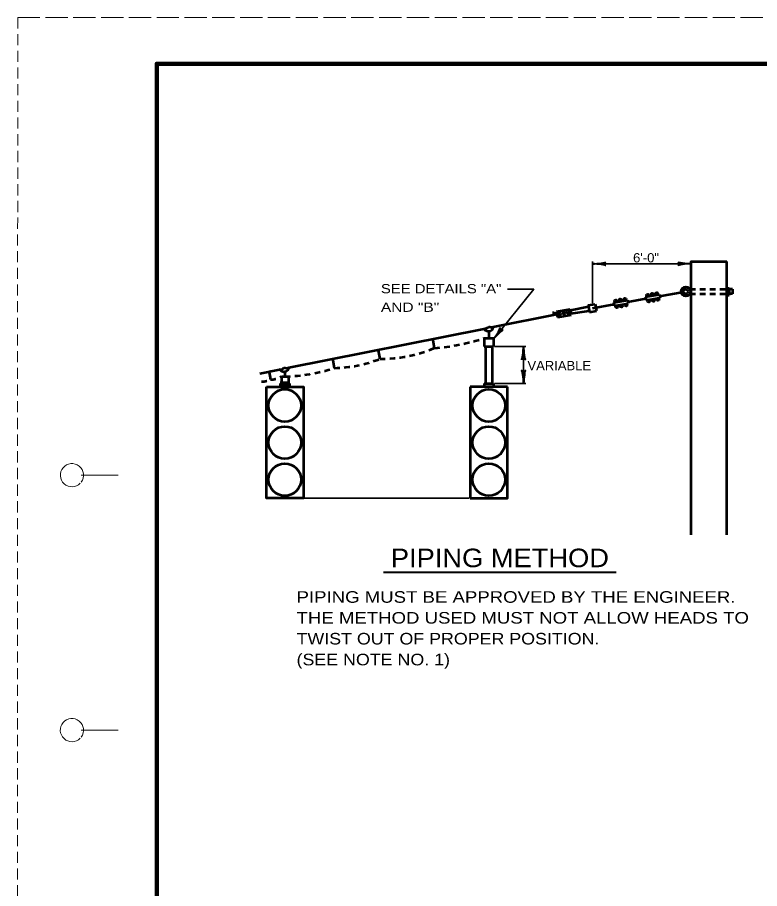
# Model space of a CAD drawing. Extents: x -286 to 394, y -156 to 284.
# Drawn here: x -286.4 to -126.2, y 96.5 to 284.5 of the extents above; entities that cross this region are included whole.
import ezdxf
from ezdxf.enums import TextEntityAlignment as Align

# ---------------------------------------------------------------- set-up
doc = ezdxf.new("R2010")
doc.units = 0
doc.header["$LTSCALE"] = 0.8
for name, pattern in [('LONG_DASHED', [7.5, 6, -1.5]), ('MEDIUM_DASHED', [4.5, 3, -1.5]), ('SHORT_DASHED', [2.7, 1.5, -1.2])]:
    doc.linetypes.add(name, pattern=pattern)
doc.layers.add('1', color=7, linetype='Continuous', lineweight=53)
doc.layers.add('61', color=7, linetype='Continuous', lineweight=35)

msp = doc.modelspace()

# ---------------------------------------------------------------- hatches: boundary and pattern name
at = {"layer": '1'}
for points in [[(-156.0439, 223.4737, 1), (-156.5439, 223.4737, 1)], [(-155.0623, 223.6436, 1), (-155.5623, 223.6436, 1)], [(-150.1246, 224.52, 1), (-150.6246, 224.52, 1)], [(-149.1505, 224.6899, 1), (-149.6505, 224.6899, 1)], [(-148.8976, 223.4474, 1), (-149.3976, 223.4474, 1)], [(-148.1689, 224.8598, 1), (-148.6689, 224.8598, 1)], [(-147.9197, 223.6212, 1), (-148.4197, 223.6212, 1)], [(-157.018, 223.3037, 1), (-157.518, 223.3037, 1)], [(-156.7877, 222.0499, 1), (-157.2877, 222.0499, 1)], [(-155.791, 222.2312, 1), (-156.291, 222.2312, 1)], [(-154.8132, 222.4049, 1), (-155.3132, 222.4049, 1)], [(-149.8943, 223.2662, 1), (-150.3943, 223.2662, 1)], [(-169.2135, 220.5049, 1), (-169.7135, 220.5049, 1)], [(-168.2289, 220.6797, 1), (-168.7289, 220.6797, 1)], [(-167.2444, 220.8512, 1), (-167.7444, 220.8512, 1)]]:
    msp.add_hatch(color=256, dxfattribs=at).paths.add_polyline_path(points)

# ---------------------------------------------------------------- linework, layer by layer
at = {"layer": '1', "linetype": 'MEDIUM_DASHED', "lineweight": 13}
msp.add_line((-286.3491, 284.4627), (-286.4091, -155.5772), dxfattribs=at)
at = {"layer": '1', "lineweight": 35}
for p, q in [((-162.2735, 222.8329), (-162.2735, 231.8187)), ((-162.2735, 231.3187), (-141.0055, 231.3187)), ((-183.4202, 213.4922), (-176.6702, 213.4922)), ((-177.1702, 213.4922), (-177.1702, 205.4922)), ((-183.4202, 205.4922), (-176.6702, 205.4922)), ((-224.4294, 180.7422), (-188.9294, 180.7422))]:
    msp.add_line(p, q, dxfattribs=at)
at = {"layer": '1'}
for p, q in [((-133.3001, 172.8187), (-133.3001, 231.8187)), ((-133.3001, 226.0687), (-132.8001, 226.0687)), ((-132.8001, 226.0687), (-132.8001, 224.5687)), ((-132.0501, 225.8187), (-132.8001, 225.8187)), ((-132.0501, 225.8187), (-132.0501, 224.8187)), ((-154.6942, 223.1097), (-150.7551, 223.8047)), ((-150.8202, 224.1741), (-147.8659, 224.6953)), ((-150.8202, 224.1741), (-150.6899, 223.4353)), ((-150.6899, 223.4353), (-147.7356, 223.9566)), ((-147.8659, 224.6953), (-147.7356, 223.9566)), ((-147.8007, 224.3258), (-142.593, 225.2447)), ((-133.3001, 224.5687), (-132.8001, 224.5687)), ((-132.0501, 224.8187), (-132.8001, 224.8187)), ((-167.0691, 221.3078), (-163.1517, 222.1257)), ((-163.1952, 222.3719), (-161.7179, 222.6324)), ((-163.1952, 222.3719), (-162.9346, 220.8947)), ((-162.3263, 221.7637), (-157.6485, 222.5885)), ((-161.7179, 222.6324), (-161.4574, 221.1552)), ((-157.7137, 222.9578), (-154.7593, 223.4791)), ((-157.7137, 222.9578), (-157.5833, 222.2191)), ((-157.5833, 222.2191), (-154.629, 222.7403)), ((-154.7593, 223.4791), (-154.629, 222.7403)), ((-183.73, 217.6792), (-169.9582, 220.4174)), ((-169.9582, 220.4174), (-170.9607, 220.8003)), ((-170.0668, 221.0329), (-167.1125, 221.554)), ((-170.0668, 221.0329), (-169.8498, 219.8019)), ((-169.8498, 219.8019), (-166.8953, 220.323)), ((-167.1125, 221.554), (-166.8953, 220.323)), ((-166.9387, 220.5692), (-162.978, 221.1408)), ((-162.9346, 220.8947), (-161.4574, 221.1552)), ((-227.8206, 208.9131), (-185.7757, 217.2725)), ((-184.6702, 216.8145), (-184.6702, 215.2422)), ((-196.8388, 215.3279), (-196.4478, 213.1117)), ((-185.6702, 215.2422), (-183.6702, 215.2422)), ((-185.6702, 215.2422), (-185.6702, 213.4922)), ((-183.6702, 215.2422), (-183.6702, 213.4922)), ((-208.6111, 212.9873), (-208.2202, 210.7711)), ((-185.6702, 213.4922), (-183.6702, 213.4922)), ((-185.4202, 213.4922), (-185.4202, 205.4922)), ((-183.9202, 213.4922), (-183.9202, 205.4922)), ((-218.4213, 211.0368), (-218.0304, 208.8206)), ((-234.0739, 207.6699), (-229.8589, 208.5078)), ((-232.1557, 208.3061), (-231.8083, 206.3364)), ((-229.4294, 206.9922), (-227.9294, 206.9922)), ((-229.4294, 206.9922), (-229.4294, 205.4922)), ((-228.6794, 208.0803), (-228.6794, 206.9922)), ((-227.9294, 206.9922), (-227.9294, 205.4922)), ((-229.6794, 205.4922), (-229.6794, 204.7422)), ((-227.6794, 205.4922), (-227.6794, 204.7422)), ((-185.6702, 205.4922), (-183.6702, 205.4922)), ((-185.6702, 205.4922), (-185.6702, 204.7422)), ((-183.6702, 205.4922), (-183.6702, 204.7422)), ((-188.6702, 204.7422), (-188.6702, 180.7422)), ((-180.6702, 204.7422), (-188.6702, 204.7422))]:
    msp.add_line(p, q, dxfattribs=at)
at = {"layer": '1', "linetype": 'SHORT_DASHED'}
for p, q in [((-141.3001, 225.8187), (-133.3001, 225.8187)), ((-141.3001, 224.8187), (-133.3001, 224.8187))]:
    msp.add_line(p, q, dxfattribs=at)
at = {"layer": '1', "lineweight": 90}
msp.add_line((-229.6794, 205.4922), (-227.6794, 205.4922), dxfattribs=at)
at = {"layer": '1', "lineweight": 40}
msp.add_line((-207.3756, 164.7691), (-157.1618, 164.7691), dxfattribs=at)
at = {"layer": '1'}
for points in [[(-141.0055, 172.8187), (-141.0055, 231.8187), (-133.3001, 231.8187)], [(-185.8869, 217.3713), (-185.4247, 216.9603), (-184.9111, 216.772), (-184.329, 216.8748), (-183.901, 217.1658), (-183.7641, 217.5768), (-183.6784, 217.7995)], [(-229.9754, 208.6114), (-229.5132, 208.2004), (-228.9996, 208.0121), (-228.4175, 208.1148), (-227.9895, 208.4059), (-227.8526, 208.8169), (-227.7669, 209.0396)], [(-188.6702, 180.7422), (-180.6702, 180.7422), (-180.6702, 204.7422)]]:
    msp.add_lwpolyline(points, dxfattribs=at)
at = {"layer": '1', "lineweight": 35}
msp.add_lwpolyline([(-183.6858, 215.0694), (-174.9799, 225.8014), (-180.608, 225.8014)], dxfattribs=at)
at = {"layer": '1'}
msp.add_lwpolyline([(-232.6794, 204.7422), (-224.6794, 204.7422), (-224.6794, 180.7422), (-232.6794, 180.7422)], close=True, dxfattribs=at)
for centre, radius in [((-142.1661, 225.3187), 1), ((-142.1731, 225.3187), 0.5), ((-156.2939, 223.4737), 0.25), ((-155.3123, 223.6436), 0.25), ((-150.3746, 224.52), 0.25), ((-149.4005, 224.6899), 0.25), ((-149.1476, 223.4474), 0.25), ((-148.4189, 224.8598), 0.25), ((-148.1697, 223.6212), 0.25), ((-157.268, 223.3037), 0.25), ((-157.0377, 222.0499), 0.25), ((-156.041, 222.2312), 0.25), ((-155.0632, 222.4049), 0.25), ((-150.1443, 223.2662), 0.25), ((-169.4635, 220.5049), 0.25), ((-168.4789, 220.6797), 0.25), ((-167.4944, 220.8512), 0.25), ((-228.6902, 200.7396), 3.5), ((-184.6595, 200.7396), 3.5), ((-228.6902, 192.7395), 3.5), ((-184.6595, 192.7395), 3.5), ((-228.6902, 184.7393), 3.5), ((-184.6595, 184.7393), 3.5)]:
    msp.add_circle(centre, radius, dxfattribs=at)
for centre, radius, start, end in [((-186.0064, 219.3509), 2.0912, 276.33147, 309.71183), ((-184.0829, 219.46), 1.8154, 251.12381, 281.20961), ((-229.6386, 209.386), 0.9101, 256.47804, 331.55185), ((-228.2784, 210.0365), 1.2201, 242.67705, 291.88866)]:
    msp.add_arc(centre, radius, start, end, dxfattribs=at)
at = {"layer": '1', "linetype": 'SHORT_DASHED'}
for centre, radius, start, end in [((-200.1702, 260.266), 47.301, 274.51361, 287.85124), ((-208.168, 241.2811), 30.5102, 269.90064, 292.58925), ((-218.6223, 237.4434), 28.6289, 271.18455, 291.30556), ((-229.8019, 245.4565), 38.4807, 271.67159, 287.81274), ((-231.8234, 211.0335), 4.6971, 270.18364, 300.64191), ((-233.4882, 209.5484), 3.6248, 265.8455, 297.6098)]:
    msp.add_arc(centre, radius, start, end, dxfattribs=at)
at = {"layer": '1', "lineweight": 40}
for centre, major_axis, ratio, start_param, end_param in [((-161.153, 231.1071), (-1.7565, 0.1757), 0.07063, 3.14071475, 5.41810995), ((-161.153, 231.1071), (-1.7565, 0.1757), 0.07063, 3.14071475, 5.41810995), ((-161.1823, 231.595), (-1.7857, -0.1562), 0.122415, 0.89635335, 3.14159265), ((-161.1823, 231.595), (-1.7857, -0.1562), 0.122415, 0.89635335, 3.14159265), ((-142.0967, 231.0424), (1.7857, 0.1562), 0.122415, 0.89635335, 3.14159265), ((-142.126, 231.5303), (1.7565, -0.1757), 0.07063, 3.14071475, 5.41810995), ((-183.213, 216.0909), (-1.0037, -1.4852), 0.122415, 0.89635335, 3.14159265), ((-182.8156, 215.8063), (1.243, 1.2534), 0.07063, 6.28230741, 8.55970261), ((-177.3819, 212.3717), (0.1757, 1.7565), 0.07063, 3.14071475, 5.41810995), ((-177.3819, 212.3717), (0.1757, 1.7565), 0.07063, 3.14071475, 5.41810995), ((-176.894, 212.4011), (-0.1562, 1.7857), 0.122415, 0.89635335, 3.14159265), ((-176.894, 212.4011), (-0.1562, 1.7857), 0.122415, 0.89635335, 3.14159265), ((-177.4465, 206.5834), (0.1562, -1.7857), 0.122415, 0.89635335, 3.14159265), ((-176.9586, 206.6128), (-0.1757, -1.7565), 0.07063, 3.14071475, 5.41810995)]:
    msp.add_ellipse(centre, major_axis=major_axis, ratio=ratio, start_param=start_param, end_param=end_param, dxfattribs=at)
at = {"layer": '61', "linetype": 'LONG_DASHED', "lineweight": 13}
msp.add_line((-286.3491, 284.4627), (393.6709, 284.4627), dxfattribs=at)
at = {"layer": '61', "lineweight": 13}
for p, q in [((-272.6291, 185.7027), (-264.6491, 185.7227)), ((-272.6491, 130.7028), (-264.6491, 130.7028))]:
    msp.add_line(p, q, dxfattribs=at)
at = {"layer": '61', "lineweight": 158}
msp.add_lwpolyline([(382.6909, 274.4627), (-256.3491, 274.4627), (-256.3491, -145.5572)], dxfattribs=at)
at = {"layer": '61', "lineweight": 13}
for centre, end in [((-274.6513, 185.704), 316.23216), ((-274.6513, 130.704), 315.37577)]:
    msp.add_arc(centre, 2.5, 323.13009, end, dxfattribs=at)

# ---------------------------------------------------------------- texts
at = {"layer": '1'}
for s, height, width, p in [('6\'-0"', 2, 1.05, (-150.737, 231.6056)), ('VARIABLE', 2, 1.05, (-169.4628, 208.341)), ('PIPING METHOD', 4, 1.1, (-182.2792, 165.8498))]:
    msp.add_text(s, height=height, dxfattribs=dict(at, width=width)).set_placement(p, align=Align.CENTER)
for s, height, width, p in [('SEE DETAILS "A"', 2, 1.2, (-207.9602, 224.9428)), ('AND "B"', 2, 1.25, (-207.9602, 220.9428)), ('PIPING MUST BE APPROVED BY THE ENGINEER.', 2.5, 1.2, (-226.1648, 158.1746)), ('THE METHOD USED MUST NOT ALLOW HEADS TO', 2.5, 1.2, (-226.1648, 153.6746)), ('TWIST OUT OF PROPER POSITION.', 2.5, 1.15, (-226.1648, 149.1746)), ('(SEE NOTE NO. 1)', 2.5, 1.15, (-226.1648, 144.6746))]:
    msp.add_text(s, height=height, dxfattribs=dict(at, width=width)).set_placement(p)

doc.saveas('drawing.dxf')
